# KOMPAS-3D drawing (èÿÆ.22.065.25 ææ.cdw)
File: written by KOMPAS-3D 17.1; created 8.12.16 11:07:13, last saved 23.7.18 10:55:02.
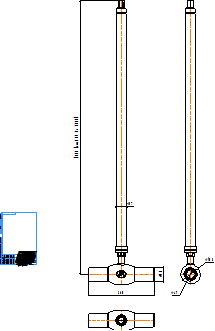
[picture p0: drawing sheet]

Sheet 1: A4, portrait

Title block, sheet 1: name: КШТ.22.065.25 С/С; sheets: 1; organisation: ООО "Торговый дом АДЛ"; sheet format: A4; stored path: C:\Users\kka\KOMPAS_Work\Модели кранов для исследований\DN65\С удлинением\КШГ.35.050.25 СС ГЧ _ Шаровой кран БИВАЛ Ду50 Ру2,5 МПа полнопроходной под приварку, c удлинением штока H=950 Габаритный чертеж Lстр600.cdw

Views: Вид 1, Спереди
Referenced files in C:\Users\kka\KOMPAS_Work\Модели кранов для исследований\DN65\С удлинением\: КШТ.22.065.25 СС.a3d
Referenced files in C:\Users\kka\KOMPAS_Work\Модели кранов для исследований\DN65\: АПТА.0203-973.04.01 _ Корпус крана Ду65.m3d, АПТА.0203-2617.13.01 _ Корпус штока Ду65-80.m3d, АПТА.0203-2617.12.04 _ Шайба фрикционная Ду65-80.m3d, АПТА.0203-2617.12.03 _ Шайба штока Ду65-80.m3d, АПТА.0203-2617.12.02 _ Шток Ду65-80.m3d, АПТА.0203-2617.11.03 - Кольцо прокладочное Ду65-80.m3d, АПТА.0203-2617.11.02 _ Подкладка для кольца Ду65-80.m3d, Кольцо Viton 19.2x3.m3d, Кольцо EPDM 19.2x3.m3d, СТ.818.013.02 _ Подшипник скольжения 20х10.m3d, АПТА.0203-2617.11.01 _ Шар Ду65.m3d, АПТА.0203-973.000.00 _ Кран шаровой сварной Ду65 (труба по ГОСТ).a3d!АПТА.0203-973.000.00!Деталь (локальная).m3d, АПТА.0203-973.000.00 _ Кран шаровой сварной Ду65 (труба по ГОСТ).a3d!АПТА.0203-973.000.00!Деталь (локальная) 1.m3d, АПТА.0203-2617.02.03 _ Пружина тарельчатая Ду65.m3d, АПТА.0203-2617.02.05 _ Уплотнение седловое Ду65.m3d, АПТА.0203-2617.02.04 _ Кольцо опорное Ду65.m3d, АПТА.203-973.03.01 _ Патрубок сварной точенный Ду65 (труба по ГОСТ).m3d, АПТА.0203-2617.02.02 _ Кольцо горловое Ду65.m3d, АПТА.0203-2617.03.02 _ Втулка Ду65-80.m3d, АПТА.0203-2617.03.01 _ Рукоятка Ду65-80.m3d, АПТА.0203-2617.03.03 _ Ухватка Ду65-200.m3d, АПТА.0203-2617.02.00  _ Рукоятка регулирующего крана Ду65-80.a3d, АПТА.0203-973.000.00 _ Кран шаровой сварной Ду65 (труба по ГОСТ).a3d
Referenced files: Подшипник скольжения 20х10.m3d
Referenced files in C:\Program Files\ASCON\KOMPAS-3D v17\Libs\PartLib\DATA\VAULT\methods\kompas\3d\: PLib_Pin_3128_712.m3d, PLib_Pins_GOST_14229_911.m3d, PLib_Check_spring_rings_GOST_13942_911.m3d, PLib_Screw_900.m3d, PLib_Screw_GOST_11074-84_900.m3d
Referenced files in C:\Users\kka\KOMPAS_Work\Удлинения БИВАЛ ф. ADL\Небюджет\Удлинения_2010\Верхушки Ду20-100\65-80\: Спец Фланец Ду65-80.m3d, Корпус штока65.m3d, Шток.m3d, Шайба_штокаДу65-80.m3d, ш_фрикц.m3d, Сборка.a3d
Referenced files in C:\Users\kka\KOMPAS_Work\!Trash\Электроприводы\: SQ05.2.m3d
Referenced files in C:\Users\kka\KOMPAS_Work\Удлинения БИВАЛ ф. ADL\Небюджет\Удлинения_2010\УШДн65-80\: Прокладка65-80.m3d, фл_нижн65-80.m3d, кольцо_зап.m3d, корп65-80.m3d, адаптер65-80нижн.m3d, удлин65-80.m3d, УШ.271.00.00.a3d
Referenced files in C:\Users\kka\KOMPAS_Work\Удлинения БИВАЛ ф. ADL\Небюджет\Удлинения_2010\УШДн40-50\: УШ.261.01.01 _ Головка штока Ду20-80.m3d, УШ.261.00.05 _ Крышка корпуса Ду20-80.m3d
Referenced files in C:\Users\kka\KOMPAS_Work\!Trash\АГТО 099.00.00 Кран для выставки Ду150 ПП П-Э патрубки\Удлинение 200\: Кольцо 036-041-30-1-2 ГОСТ 9833-73ГОСТ 18829-73.m3d
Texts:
  Klimkovich
  ADL
  (от 287 до 5000)
  УШ.271.00.00
  Рама для чертежей
  Лит-Масса-Масштаб
  Материал-Предприятие
  Масштаб
  Изм.
  Лист
  № докум.
  Подп.
  Дата
  Лит.
  Разраб.
  Пров.
  Т.контр.
  Листов
  Внимание! Данный продукт является объектом авторского права ООО «Торговый Дом АДЛ».
  Запрещается изменение, копирование, распространение
  (в том числе путем копирования на другие сайты и ресурсы в Интернете)
  или любое иное использование информации и объектов без предварительного
  согласия правообладателя (ООО «Торговый Дом АДЛ»).
  Н.контр.
  Утв.
  Изменение
  Номер документа
  Подпись
  Обозначение документа
  Наименование изделия
  Масса изделия по ГОСТ 2.109-73
  Порядковый номер листа
  Общее количество листов в документе
  Характер работы, выполненной лицом, подписавшим документ
  Наименование или индекс предприятия, выпускающего документ
  Инв. № подл.
  Подп. и дата
  Взам. инв. №
  Инв. № дубл.
  Инвентарный номер подлинника по ГОСТ 2.501-68
  Подпись принявшего подлинник в отдел технической документации
  Инвентарный номер подлинника, взамен которого выпущен данный подлинник
  Инвентарный номер дубликата по ГОСТ 2.502-68
  Подпись принявшего дубликат в отдел технической документации
  Справ. №
  Перв. примен.
  Обозначение документа, взамен или на основании которого выпущен данный документ
  Обозначение документа, в котором впервые записан данный документ
  Подпись лица, копировавшего чертеж
  Обозначение формата листа
  !Рама для чертежа
  Корпус крана Ду65
  АПТА.0203-973.04.01
  Корпус штока Ду65-80
  АПТА.0203-2617.13.01
  Шайба фрикционная Ду65-80
  АПТА.0203-2617.12.04
  Шайба штока Ду65-80
  АПТА.0203-2617.12.03
  Шток Ду65-80
  АПТА.0203-2617.12.02
  Кольцо прокладочное Ду65-80
  АПТА.0203-2617.11.03
  Подкладка для кольца Ду65-80
  АПТА.0203-2617.11.02
  Кольцо Viton 19.2x3
  Кольцо EPDM 19.2x3
  СТ.818.013.02
  Шар Ду65
  АПТА.0203-2617.11.01
  Деталь (локальная)
  Пружина тарельчатая Ду65
  АПТА.0203-2617.02.03
  Уплотнение седловое Ду65
  АПТА.0203-2617.02.05
  Кольцо опорное Ду65
  АПТА.0203-2617.02.04
  Патрубок сварной точенный Ду65 (труба по ГОСТ)
  АПТА.203-973.03.01
  Кольцо горловое Ду65
  АПТА.0203-2617.02.02
  Штифт 6x36 ГОСТ 3128-70
  Втулка Ду65-80
  Рукоятка Ду65-80
  АПТА.0203-2617.03.01
  Ухватка Ду65-200
  АПТА.0203-2617.03.03
  Ручка Ду65-80
  АПТА.0203-2617.03.00
  Штифт A.8x35 ГОСТ 14229-93
  Спец Фланец Ду65-80
  SQ05.2 220В
  Кран шаровой сварной Ду65 (труба по ГОСТ)
  АПТА.0203-973.000.00
  Штифт 2.6Х30 ГОСТ 3128-70
  Штифт 2.8Х36 ГОСТ 3128-70
  Сборка
  Головка штока Ду20-80
  УШ.261.01.01
  Корпус
  Удлинитель
  Штифт 2.10Х45 ГОСТ 3128-70
  Крышка корпуса Ду20-80
  УШ.261.00.05
  Кольцо A36.65Г ГОСТ 13942-86
  Винт М6-6gX25.109.30ХГСА ГОСТ 11738-84
  Винт А.М6-6gx6.14H ГОСТ 11074-93
  Кольцо 036-041-30-1-2 ГОСТ 9833-73/ГОСТ 18829-73
  Удлинитель штока Ду65-80
  УШ.271.01.00
  Штифт 6x30 ГОСТ 3128-70
  Удлинение штока Ду65-80
Dimensions and other numbers on the sheet: 76; 1500; 57; 360; 1:1; 1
